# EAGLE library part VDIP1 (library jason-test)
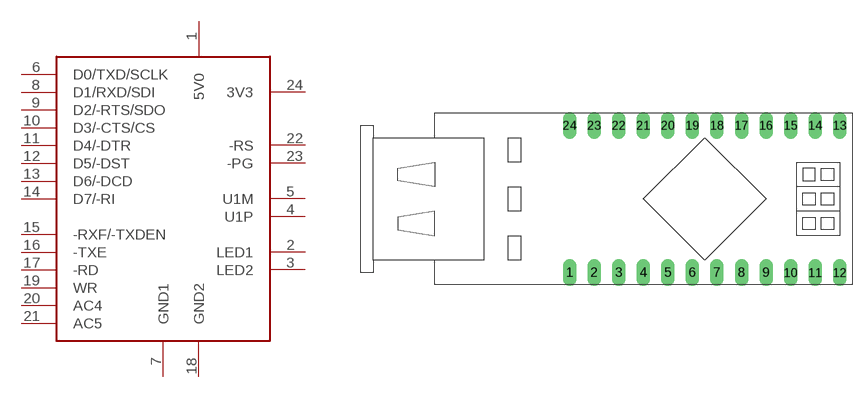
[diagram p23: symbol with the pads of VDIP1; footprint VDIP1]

Designator prefix -

## VDIP1  [VDIP1]
1  5V0  pwr
2  LED1  out
3  LED2  out
4  U1P
5  U1M
6  D0/TXD/SCLK
7  GND1  pwr
8  D1/RXD/SDI
9  D2/-RTS/SDO
10  D3/-CTS/CS
11  D4/-DTR
12  D5/-DST
13  D6/-DCD
14  D7/-RI
15  -RXF/-TXDEN
16  -TXE
17  -RD
18  GND2  pwr
19  WR
20  AC4
21  AC5
22  -RS  in
23  -PG  in
24  3V3

## Footprint VDIP1 (pad centres in mm)
Vinculum VDIP1 http://www.vinculum.com/images/vdip1-001.jpg
drill 0.8 pad 1.397 long: 1 0,-7.62; 2 2.54,-7.62; 3 5.08,-7.62; 4 7.62,-7.62; 5 10.16,-7.62; 6 12.7,-7.62; 7 15.24,-7.62; 8 17.78,-7.62; 9 20.32,-7.62; 10 22.86,-7.62; 11 25.4,-7.62; 12 27.94,-7.62; 13 27.94,7.62; 14 25.4,7.62; 15 22.86,7.62; 16 20.32,7.62; 17 17.78,7.62; 18 15.24,7.62; 19 12.7,7.62; 20 10.16,7.62; 21 7.62,7.62; 22 5.08,7.62; 23 2.54,7.62; 24 0,7.62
